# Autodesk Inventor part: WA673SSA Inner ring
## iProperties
Category: PARTsolutions
Created: 2011-07
Part Number: WA673SSA Inner ring
Catalog Web Link: www.cadenas.de
Description: Six types ir - Metric system sizes
Document SubType Name: Modeling
Designer: PARTsolutions
Density: 1 g/cm^3
NB: WA673SSA Inner ring
NN: Six types ir
NT: Metric system sizes
NBSYN: $ORDER. Inner ring
LINA: WA673SSA Inner ring
SD: 3.0
D: 6
B: 2.0
R: 0.08
ORDER: WA673SSA
CR: 242
COR: 94
CRF: 25
CORF: 9,5
LSG: 60 000
LSO: 71 000
MASS: 0.20
D1: 7.2
D2: 7.2
C1: 0.6
C2: 0.6
ORDER1: 673
WSS: WA673SSA
WDS: SSA
UTWF: FL673
FORSS: FLWA673SA
FORDS: SSA
DA1: 3,6
DA2: 4,1
DA: 5,4
RAS: 0,08
MASS1: 0.26
B1: 2.5
VERS: 3
X: 1.500
N: 9
O: 14.130
RB: 0.444
KT: DUMMY
SUPPLIER: NTN
ARTICLENO: WA673SSA Inner ring
BOMINFO: WA673SSA Inner ring
CREATOR: CADENAS GmbH
PSOL_IDENT_0: {\\10.0.0.251\ps_data\23d-libs\ntn\ball_roller_bearings\miniature_extra_small_bb\metric_system_sizes
PSOL_IDENT_1: \mss_ir.prj},189 {VTYP=3D},{NB=WA673SSA Inner ring},{LINA=WA673SSA Inner ring},{NN=Six types ir},{DA
PSOL_IDENT_2: TE=11.12.2007 08:48:23},{GEOMDATE=28.06.2007 12:57:00},{VERSION=},{LINEID=12590},{LINESUBID=-1},{WBV
PSOL_IDENT_3: AR=}  {NB=WA673SSA Inner ring},{LINA=WA673SSA Inner ring},{KT=DUMMY},{IDNR=},{SD=3.0},{D=6},{B=2.0},
PSOL_IDENT_4: {R=0.08},{ORDER=WA673SSA},{CR=242},{COR=94},{CRF=25},{CORF=9,5},{LSG=60 000},{LSO=71 000},{MASS=0.20
PSOL_IDENT_5: },{D1=7.2},{D2=7.2},{C1=0.6},{C2=0.6},{ORDER1=673},{WSS=WA673SSA},{WDS=SSA},{UTWF=FL673},{FORSS=FLWA
PSOL_IDENT_6: 673SA},{FORDS=SSA},{DA1=3,6},{DA2=4,1},{DA=5,4},{RAS=0,08},{MASS1=0.26},{B1=2.5},{VERS=3},{X=1.5},{N
PSOL_IDENT_7: =9},{O=14.13},{RB=0.444}
Title: WA673SSA Inner ring
Author: Cadenas PARTsolutions
Comments: Metric system sizes
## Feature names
1. Revolution1
